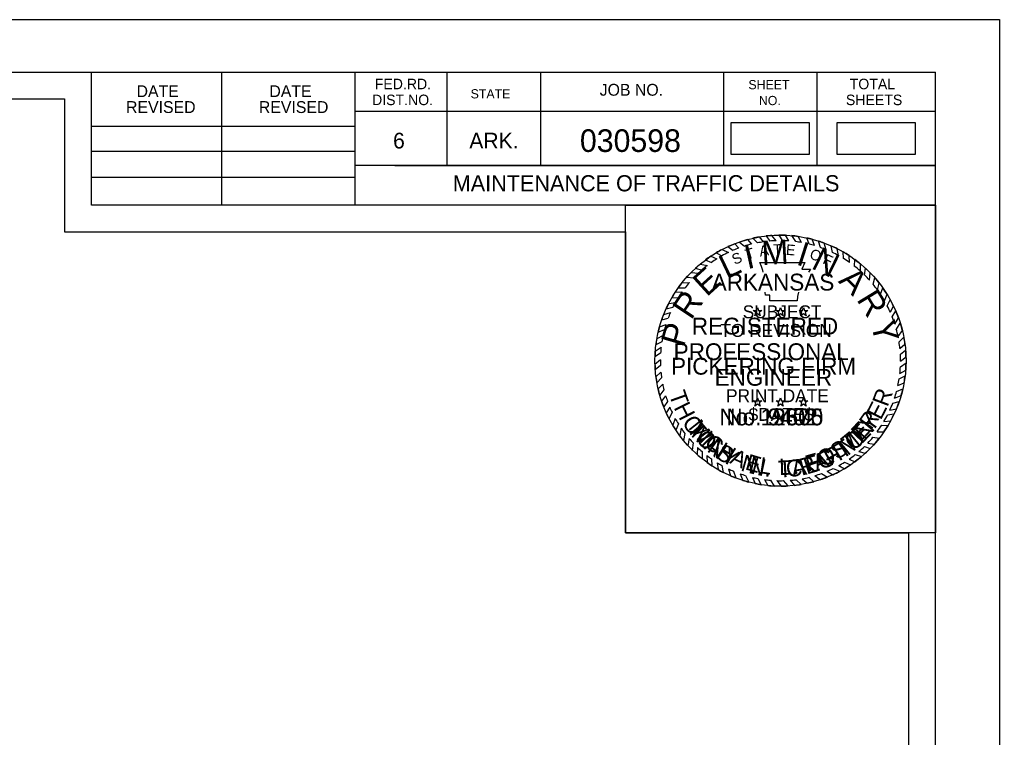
# Model space of a CAD drawing. Extents: x 1368648 to 1927880, y -1037443 to 380209.
# Drawn here: x 1373048.4 to 1373412.1, y 379486.2 to 379752.7 of the extents above; entities that cross this region are included whole.
import ezdxf

# ---------------------------------------------------------------- set-up
doc = ezdxf.new("R2010")
doc.units = 0
for name, color, linetype in [('Default', 7, 'Continuous'), ('R_Border', 7, 'Continuous'), ('R_Border Notes', 7, 'Continuous'), ('R_No Plot', 7, 'Continuous'), ('STAMP_PE_CRAFTON', 7, 'Continuous'), ('STAMP_PE_FOSTER', 7, 'Continuous'), ('STAMP_PE_SEAL-INFO', 7, 'Continuous'), ('STAMP_PE_TAEGTMEYER', 7, 'Continuous'), ('STAMP_PE_TXT', 7, 'Continuous'), ('STAMP_PRELIMINARY', 7, 'Continuous')]:
    doc.layers.add(name, color=color, linetype=linetype)

msp = doc.modelspace()

# ---------------------------------------------------------------- linework, layer by layer
at = {"layer": 'Default'}
for points in [[(1373312.37, 379702.78), (1373341.54, 379702.78), (1373341.54, 379714.33), (1373312.37, 379714.33)], [(1373351.72, 379702.78), (1373380.89, 379702.78), (1373380.89, 379714.33), (1373351.72, 379714.33)]]:
    msp.add_lwpolyline(points, close=True, dxfattribs=at)
at = {"layer": 'R_Border'}
for p, q in [((1371807.4, 379733.26), (1373388.3, 379733.26)), ((1373075.1, 379683.86), (1373075.1, 379733.26)), ((1373123.5, 379683.86), (1373123.5, 379733.26)), ((1373172.8, 379733.26), (1373172.8, 379683.86)), ((1373207, 379733.26), (1373207, 379698.56)), ((1373241.7, 379733.26), (1373241.7, 379698.56)), ((1373309.6, 379733.26), (1373309.6, 379698.56)), ((1373344.3, 379733.26), (1373344.3, 379698.56)), ((1373388.3, 378705.96), (1373388.3, 379733.26)), ((1373388.3, 379718.56), (1373172.8, 379718.56)), ((1373388.3, 379718.66), (1373388.3, 379718.66)), ((1373075.1, 379713.16), (1373172.8, 379713.16)), ((1373075.1, 379703.86), (1373172.8, 379703.86)), ((1373388.3, 379698.56), (1373172.8, 379698.56)), ((1373187.6, 379698.56), (1373388.3, 379698.56)), ((1373075.1, 379694.16), (1373172.8, 379694.16)), ((1373388.3, 379683.86), (1373075.1, 379683.86))]:
    msp.add_line(p, q, dxfattribs=at)
at = {"layer": 'R_No Plot'}
for points in [[(1371745.37, 379752.73), (1373412.07, 379752.73), (1373412.07, 378686.04), (1371745.37, 378686.04)], [(1373378.3, 379229.61), (1371817.4, 379229.61), (1371817.4, 379723.26), (1373065.1, 379723.26), (1373065.1, 379673.86), (1373152.8, 379673.86), (1373273.3, 379673.86), (1373273.3, 379562.19), (1373378.3, 379562.19)], [(1371817.4, 379723.26), (1373065.1, 379723.26), (1373065.1, 379673.86), (1373152.8, 379673.86), (1373273.3, 379673.86), (1373273.3, 379562.19), (1373378.3, 379562.19), (1373378.3, 378715.96), (1371817.4, 378715.96)], [(1373273.3, 379683.86), (1373388.3, 379683.86), (1373388.3, 379562.19), (1373273.3, 379562.19)]]:
    msp.add_lwpolyline(points, close=True, dxfattribs=at)
at = {"layer": 'STAMP_PE_SEAL-INFO'}
for p, q in [((1373313.86, 379669.49), (1373315.34, 379667.87)), ((1373315.6, 379670.13), (1373317.51, 379668.61)), ((1373318.56, 379671.04), (1373320, 379669.31)), ((1373320.5, 379671.53), (1373322.28, 379669.81)), ((1373322.91, 379672.01), (1373324.4, 379670.17)), ((1373325.49, 379672.38), (1373326.89, 379670.46)), ((1373329.16, 379670.61), (1373327.6, 379672.57)), ((1373331.65, 379670.63), (1373330.26, 379672.68)), ((1373333.94, 379670.53), (1373332.65, 379672.65)), ((1373336.47, 379670.27), (1373335.01, 379672.49)), ((1373338.6, 379669.95), (1373337.31, 379672.23)), ((1373341.41, 379669.36), (1373340.54, 379671.65)), ((1373343.42, 379668.81), (1373342.62, 379671.16)), ((1373345.68, 379668.08), (1373344.97, 379670.48)), ((1373347.77, 379667.28), (1373347.05, 379669.76)), ((1373306.93, 379666.1), (1373309.09, 379664.99)), ((1373309.17, 379667.36), (1373311.49, 379666.23)), ((1373311.32, 379668.42), (1373313.27, 379667.04)), ((1373350.08, 379666.25), (1373349.56, 379668.74)), ((1373352.31, 379665.11), (1373351.87, 379667.65)), ((1373354.24, 379663.97), (1373354.04, 379666.48)), ((1373302.89, 379663.55), (1373305.17, 379662.53)), ((1373305, 379664.88), (1373307.2, 379663.87)), ((1373323.17, 379662.52), (1373339.89, 379662.52)), ((1373323.78, 379660.99), (1373323.17, 379662.52)), ((1373339.89, 379662.52), (1373338.77, 379660.07)), ((1373356.42, 379662.54), (1373356.26, 379665.12)), ((1373358.22, 379661.21), (1373358.39, 379663.64)), ((1373297.61, 379658.8), (1373300.33, 379658.59)), ((1373299.29, 379660.41), (1373301.58, 379659.72)), ((1373301.01, 379661.92), (1373303.66, 379661.41)), ((1373324.3, 379659.5), (1373323.78, 379660.99)), ((1373324.33, 379658.93), (1373324.3, 379659.5)), ((1373338.77, 379660.07), (1373341.93, 379660.07)), ((1373341.93, 379660.07), (1373341.2, 379658.93)), ((1373360.45, 379659.35), (1373360.55, 379661.96)), ((1373362.01, 379657.88), (1373362.36, 379660.38)), ((1373363.81, 379656.02), (1373364.14, 379658.65)), ((1373294.27, 379655.02), (1373297.02, 379655.13)), ((1373296, 379657.08), (1373298.61, 379656.88)), ((1373365.18, 379654.44), (1373365.86, 379656.79)), ((1373366.8, 379652.35), (1373367.47, 379654.85)), ((1373291.71, 379651.45), (1373294.29, 379651.62)), ((1373292.88, 379653.17), (1373295.41, 379653.15)), ((1373325.29, 379650.38), (1373325.16, 379651.47)), ((1373337.47, 379651.47), (1373337.09, 379649.92)), ((1373367.9, 379650.77), (1373368.79, 379653.09)), ((1373289.32, 379647.33), (1373291.81, 379647.65)), ((1373290.48, 379649.45), (1373292.92, 379649.55)), ((1373326.86, 379650.38), (1373325.29, 379650.38)), ((1373326.86, 379648.23), (1373326.86, 379650.38)), ((1373337.01, 379648.23), (1373326.86, 379648.23)), ((1373337.09, 379649.92), (1373337.01, 379648.23)), ((1373369.44, 379648.29), (1373370.35, 379650.74)), ((1373370.44, 379646.45), (1373371.57, 379648.68)), ((1373287.46, 379643.22), (1373289.98, 379643.95)), ((1373288.38, 379645.38), (1373290.89, 379645.9)), ((1373371.59, 379644.03), (1373372.72, 379646.46)), ((1373372.29, 379642.35), (1373373.61, 379644.52)), ((1373286.71, 379641.19), (1373289.13, 379641.87)), ((1373373.27, 379639.6), (1373374.62, 379641.98)), ((1373285.41, 379636.64), (1373287.76, 379637.6)), ((1373285.93, 379638.68), (1373288.32, 379639.52)), ((1373373.81, 379637.78), (1373375.27, 379640.04)), ((1373374.47, 379634.99), (1373376.06, 379637.22)), ((1373286.8, 379633.11), (1373284.57, 379632)), ((1373287.23, 379635.41), (1373284.9, 379634.16)), ((1373374.82, 379633.09), (1373376.58, 379634.85)), ((1373286.5, 379630.94), (1373284.32, 379629.53)), ((1373375.15, 379630.54), (1373377.01, 379632.22)), ((1373375.31, 379628.45), (1373377.26, 379629.91)), ((1373286.32, 379628.81), (1373284.21, 379627.53)), ((1373286.24, 379626.34), (1373284.21, 379624.67)), ((1373375.37, 379625.86), (1373377.4, 379627.47)), ((1373286.27, 379624.31), (1373284.31, 379622.68)), ((1373375.12, 379621.3), (1373377.29, 379622.59)), ((1373375.32, 379623.83), (1373377.41, 379625.22)), ((1373286.44, 379621.83), (1373284.58, 379620.05)), ((1373286.7, 379619.69), (1373284.93, 379617.82)), ((1373374.86, 379619.36), (1373377.08, 379620.46)), ((1373287.09, 379617.39), (1373285.39, 379615.55)), ((1373287.56, 379615.3), (1373286, 379613.22)), ((1373373.87, 379614.6), (1373376.23, 379615.61)), ((1373374.41, 379616.86), (1373376.69, 379617.84)), ((1373288.18, 379613.06), (1373286.7, 379610.97)), ((1373373.14, 379612.13), (1373375.59, 379613.14)), ((1373288.88, 379610.95), (1373287.47, 379608.89)), ((1373289.71, 379608.81), (1373288.4, 379606.7)), ((1373371.39, 379607.66), (1373373.83, 379608.14)), ((1373372.46, 379610.23), (1373374.88, 379610.89)), ((1373290.57, 379606.9), (1373289.43, 379604.59)), ((1373291.75, 379604.61), (1373290.79, 379602.16)), ((1373370.59, 379605.98), (1373373.03, 379606.32)), ((1373292.92, 379602.59), (1373292, 379600.23)), ((1373293.94, 379601.03), (1373293.39, 379598.27)), ((1373368.37, 379602.08), (1373370.75, 379602.05)), ((1373369.23, 379603.49), (1373371.73, 379603.76)), ((1373295.34, 379599.08), (1373294.83, 379596.42)), ((1373296.86, 379597.19), (1373296.43, 379594.59)), ((1373365.13, 379597.64), (1373367.44, 379597.24)), ((1373366.67, 379599.61), (1373369.19, 379599.63)), ((1373298.37, 379595.5), (1373298.06, 379592.89)), ((1373299.98, 379593.87), (1373299.84, 379591.23)), ((1373361.94, 379594.18), (1373364.14, 379593.49)), ((1373363.21, 379595.48), (1373365.6, 379595.05)), ((1373301.71, 379592.31), (1373301.69, 379589.67)), ((1373303.51, 379590.84), (1373303.6, 379588.22)), ((1373305.2, 379589.59), (1373305.38, 379587)), ((1373356.25, 379589.48), (1373358.45, 379588.54)), ((1373358.56, 379591.2), (1373360.9, 379590.47)), ((1373359.91, 379592.32), (1373362.27, 379591.67)), ((1373307.33, 379588.18), (1373307.64, 379585.62)), ((1373309.09, 379587.15), (1373309.54, 379584.59)), ((1373311.49, 379585.9), (1373312.27, 379583.3)), ((1373350.42, 379586.05), (1373352.84, 379584.99)), ((1373352.46, 379587.12), (1373354.55, 379585.95)), ((1373354.54, 379588.34), (1373356.78, 379587.37)), ((1373313.35, 379585.06), (1373314.22, 379582.51)), ((1373315.82, 379584.1), (1373316.86, 379581.59)), ((1373317.86, 379583.42), (1373319, 379580.98)), ((1373320.4, 379582.73), (1373321.47, 379580.4)), ((1373322.39, 379582.3), (1373323.62, 379580.01)), ((1373338.81, 379582.23), (1373340.75, 379580.53)), ((1373341.27, 379582.75), (1373343.16, 379581.12)), ((1373343.57, 379583.37), (1373345.65, 379581.88)), ((1373346.03, 379584.18), (1373348.25, 379582.84)), ((1373348.13, 379585.01), (1373350.24, 379583.7)), ((1373324.89, 379581.89), (1373326.09, 379579.69)), ((1373327.08, 379581.66), (1373328.45, 379579.51)), ((1373329.5, 379581.52), (1373331.01, 379579.46)), ((1373331.8, 379581.51), (1373333.52, 379579.53)), ((1373334.39, 379581.65), (1373336.02, 379579.75)), ((1373336.58, 379581.88), (1373338.45, 379580.09))]:
    msp.add_line(p, q, dxfattribs=at)
for radius, start, end in [(46.61, 111.3124, 114.7026), (46.61, 105.2339, 109.0352), (44.57, 104.0352, 107.3615), (46.61, 99.7525, 102.7765), (44.57, 98.258, 101.0329), (46.61, 93.9381, 96.5517), (44.57, 92.1102, 95.0367), (46.61, 87.7298, 90.6707), (44.57, 85.9628, 88.9097), (46.61, 81.9732, 84.8236), (44.57, 79.9264, 82.696), (46.61, 75.3125, 77.9426), (44.57, 73.5575, 76.2314), (46.61, 69.6061, 72.3058), (46.61, 117.6544, 120.8099), (44.57, 115.6869, 119.1583), (44.57, 110.3086, 113.1659), (44.57, 67.6248, 70.504), (46.61, 63.1329, 66.2704), (44.57, 61.1558, 64.3784), (46.61, 56.9003, 60.0942), (46.61, 123.6199, 126.5906), (44.57, 121.9746, 125.11), (44.57, 54.9238, 58.2702), (46.61, 50.3492, 53.7159), (46.61, 135.4021, 138.3031), (44.57, 133.1331, 136.2562), (46.61, 129.7326, 132.5376), (44.57, 127.5297, 130.9683), (44.57, 48.3016, 52.0395), (46.61, 44.3405, 47.3929), (46.61, 141.6056, 144.4486), (44.57, 139.301, 142.5873), (44.57, 42.2212, 45.5512), (46.61, 38.1247, 41.2316), (46.61, 147.0072, 149.899), (44.57, 145.0197, 148.2104), (44.57, 36.135, 39.5311), (46.61, 31.9614, 35.4294), (44.57, 151.0315, 153.573), (44.57, 29.9032, 33.6645), (46.61, 25.9391, 29.0125), (46.61, 152.864, 155.5189), (44.57, 156.3402, 159.2319), (44.57, 23.7732, 27.2211), (46.61, 19.9538, 23.3141), (46.61, 158.4077, 161.0701), (44.57, 17.6802, 21.4251), (46.61, 164.3068, 166.894), (44.57, 162.4331, 165.0013), (44.57, 11.5444, 15.2364), (46.61, 13.8421, 17.4447), (46.61, 170.0003, 172.6878), (44.57, 167.9048, 170.9039), (44.57, 5.7599, 9.0606), (46.61, 7.5852, 10.8621), (46.61, 175.7409, 178.2066), (44.57, 173.73, 176.4734), (46.61, 1.7215, 4.7268), (44.57, 179.6454, 182.2633), (44.57, 359.7329, 3.0639), (46.61, 181.7251, 184.1626), (44.57, 353.8632, 357.1274), (46.61, 355.7156, 358.9569), (46.61, 187.4204, 190.1927), (44.57, 185.4539, 188.234), (44.57, 348.0778, 351.3435), (46.61, 349.8305, 353.0885), (46.61, 193.0369, 195.9973), (44.57, 191.2274, 193.9858), (46.61, 343.8925, 347.035), (44.57, 196.9675, 199.8353), (44.57, 341.777, 345.0925), (46.61, 198.8967, 201.6281), (44.57, 202.7761, 205.4791), (44.57, 335.6038, 339.1858), (46.61, 337.3837, 340.9933), (46.61, 204.5479, 207.4328), (44.57, 208.7883, 211.7934), (44.57, 329.5549, 333.2076), (46.61, 331.4037, 334.9332), (46.61, 210.8636, 213.6571), (44.57, 214.1838, 217.2747), (44.57, 323.5851, 327.4407), (46.61, 325.4405, 328.9872), (46.61, 216.6115, 219.491), (44.57, 220.3909, 223.3056), (44.57, 316.6531, 320.3711), (46.61, 318.2846, 321.8043), (46.61, 222.48, 225.3801), (44.57, 226.2494, 229.2407), (44.57, 310.7744, 314.3161), (46.61, 312.4518, 315.6633), (46.61, 228.3665, 231.348), (44.57, 232.229, 234.9336), (44.57, 304.823, 308.5143), (46.61, 306.3721, 310.208), (46.61, 234.295, 236.9452), (44.57, 238.2223, 240.8353), (46.61, 240.1977, 242.8613), (44.57, 244.3204, 246.9486), (44.57, 292.8745, 296.1185), (44.57, 299.0768, 302.1724), (46.61, 300.621, 303.8703), (46.61, 246.576, 249.1558), (44.57, 250.3491, 253.1216), (44.57, 256.505, 259.1192), (44.57, 280.3459, 283.5814), (44.57, 286.6423, 289.9783), (46.61, 288.5709, 291.9733), (46.61, 294.6481, 298.2166), (46.61, 252.5967, 255.3252), (46.61, 258.4433, 261.1398), (44.57, 262.3783, 265.2012), (46.61, 264.1978, 267.1009), (44.57, 268.3215, 271.277), (46.61, 270.2548, 273.3361), (44.57, 274.6157, 277.4486), (46.61, 276.4239, 279.4357), (46.61, 282.3199, 285.3702)]:
    msp.add_arc((1373330.8, 379626.07), radius, start, end, dxfattribs=at)
at = {"layer": 'STAMP_PE_TXT'}
for p, q in [((1373321.7, 379643.93), (1373320.71, 379644.65)), ((1373320.71, 379644.65), (1373321.94, 379644.65)), ((1373321.32, 379642.76), (1373321.7, 379643.93)), ((1373321.94, 379644.65), (1373322.31, 379645.81)), ((1373322.31, 379645.81), (1373322.69, 379644.65)), ((1373322.69, 379644.65), (1373323.92, 379644.65)), ((1373323.92, 379644.65), (1373322.93, 379643.93)), ((1373322.93, 379643.93), (1373323.31, 379642.76)), ((1373330.19, 379643.93), (1373329.2, 379644.65)), ((1373329.2, 379644.65), (1373330.43, 379644.65)), ((1373329.81, 379642.76), (1373330.19, 379643.93)), ((1373330.43, 379644.65), (1373330.8, 379645.81)), ((1373330.8, 379645.81), (1373331.18, 379644.65)), ((1373331.18, 379644.65), (1373332.41, 379644.65)), ((1373332.41, 379644.65), (1373331.42, 379643.93)), ((1373331.42, 379643.93), (1373331.8, 379642.76)), ((1373338.68, 379643.93), (1373337.69, 379644.65)), ((1373337.69, 379644.65), (1373338.92, 379644.65)), ((1373338.3, 379642.76), (1373338.68, 379643.93)), ((1373338.92, 379644.65), (1373339.29, 379645.81)), ((1373339.29, 379645.81), (1373339.67, 379644.65)), ((1373339.67, 379644.65), (1373340.9, 379644.65)), ((1373340.9, 379644.65), (1373339.91, 379643.93)), ((1373339.91, 379643.93), (1373340.29, 379642.76)), ((1373322.31, 379643.48), (1373321.32, 379642.76)), ((1373323.31, 379642.76), (1373322.31, 379643.48)), ((1373330.8, 379643.48), (1373329.81, 379642.76)), ((1373331.8, 379642.76), (1373330.8, 379643.48)), ((1373339.29, 379643.48), (1373338.3, 379642.76)), ((1373340.29, 379642.76), (1373339.29, 379643.48)), ((1373321.7, 379610.39), (1373320.71, 379611.11)), ((1373320.71, 379611.11), (1373321.94, 379611.11)), ((1373321.94, 379611.11), (1373322.31, 379612.28)), ((1373322.31, 379612.28), (1373322.69, 379611.11)), ((1373322.69, 379611.11), (1373323.92, 379611.11)), ((1373323.92, 379611.11), (1373322.93, 379610.39)), ((1373330.19, 379610.39), (1373329.2, 379611.11)), ((1373329.2, 379611.11), (1373330.43, 379611.11)), ((1373330.43, 379611.11), (1373330.8, 379612.28)), ((1373330.8, 379612.28), (1373331.18, 379611.11)), ((1373331.18, 379611.11), (1373332.41, 379611.11)), ((1373332.41, 379611.11), (1373331.42, 379610.39)), ((1373338.68, 379610.39), (1373337.69, 379611.11)), ((1373337.69, 379611.11), (1373338.92, 379611.11)), ((1373338.92, 379611.11), (1373339.29, 379612.28)), ((1373339.29, 379612.28), (1373339.67, 379611.11)), ((1373339.67, 379611.11), (1373340.9, 379611.11)), ((1373340.9, 379611.11), (1373339.91, 379610.39)), ((1373321.32, 379609.22), (1373321.7, 379610.39)), ((1373322.31, 379609.95), (1373321.32, 379609.22)), ((1373323.31, 379609.22), (1373322.31, 379609.95)), ((1373322.93, 379610.39), (1373323.31, 379609.22)), ((1373329.81, 379609.22), (1373330.19, 379610.39)), ((1373330.8, 379609.95), (1373329.81, 379609.22)), ((1373331.8, 379609.22), (1373330.8, 379609.95)), ((1373331.42, 379610.39), (1373331.8, 379609.22)), ((1373338.3, 379609.22), (1373338.68, 379610.39)), ((1373339.29, 379609.95), (1373338.3, 379609.22)), ((1373340.29, 379609.22), (1373339.29, 379609.95)), ((1373339.91, 379610.39), (1373340.29, 379609.22))]:
    msp.add_line(p, q, dxfattribs=at)
at = {"layer": 'STAMP_PRELIMINARY'}
msp.add_circle((1373330.8, 379626.07), 46.61, dxfattribs=at)

# ---------------------------------------------------------------- texts
at = {"layer": 'R_Border'}
for s, height, p in [('DATE', 4.396, (1373091.79, 379723.94)), ('DATE', 4.396, (1373141.09, 379723.94)), ('FED.RD.', 3.91, (1373180.2, 379726.86)), ('JOB NO.', 4.396, (1373263.7, 379724.46)), ('SHEET', 3.42, (1373318.9, 379726.86)), ('TOTAL', 3.91, (1373356.5, 379726.86)), ('DIST.NO.', 3.91, (1373179.2, 379720.96)), ('STATE', 3.42, (1373215.8, 379723.46)), ('NO.', 3.42, (1373322.8, 379720.96)), ('SHEETS', 3.91, (1373355.1, 379720.96)), ('REVISED', 4.396, (1373087.89, 379718.04)), ('REVISED', 4.396, (1373137.19, 379718.04)), ('6', 5.86, (1373187, 379704.86)), ('ARK.', 5.861, (1373215.3, 379704.86))]:
    msp.add_text(s, height=height, dxfattribs=at).set_placement(p)
at = {"layer": 'R_Border Notes'}
for s, height, p in [('030598', 8.4, (1373256.36, 379703.58)), ('MAINTENANCE OF TRAFFIC DETAILS', 6, (1373209.15, 379688.95))]:
    msp.add_text(s, height=height, dxfattribs=at).set_placement(p)
at = {"layer": 'STAMP_PE_CRAFTON'}
msp.add_text('No. 12370', height=6.25, dxfattribs=at).set_placement((1373308.11, 379602.05))
for s, rotation, p in [('T', 310.7442, (1373295.63, 379600.56)), ('N', 49.2411, (1373362.22, 379596.18)), ('O', 317.6422, (1373298.97, 379596.5)), ('N', 324.4537, (1373303.2, 379592.58)), ('T', 34.1136, (1373353.69, 379589.26)), ('O', 41.8391, (1373357.98, 379592.27)), ('Y', 331.1686, (1373308.36, 379589)), ('F', 28.7821, (1373349.11, 379586.72)), ('N', 347.4752, (1373318.64, 379584.42)), ('C', 6.0117, (1373333.16, 379582.77)), ('R', 14.8189, (1373338.64, 379583.35)), ('A', 20.5125, (1373344.21, 379584.85)), ('.', 356.8926, (1373324.78, 379583.03))]:
    msp.add_text(s, height=6.25, rotation=rotation, dxfattribs=at).set_placement(p)
at = {"layer": 'STAMP_PE_FOSTER'}
msp.add_text('No. 9402', height=6.25, dxfattribs=at).set_placement((1373310.73, 379602.05))
for s, rotation, p in [('M', 308.339, (1373296.38, 379601.18)), ('R', 54.5031, (1373364.43, 379600.12)), ('E', 46.9613, (1373360.81, 379596.02)), ('I', 314.1842, (1373300.37, 379596.49)), ('C', 319.8733, (1373302.14, 379594.72)), ('T', 39.4194, (1373356.52, 379592.27)), ('H', 327.7235, (1373306.79, 379591.04)), ('O', 23.719, (1373346.2, 379586.48)), ('S', 31.7234, (1373351.76, 379589.13)), ('A', 335.7276, (1373311.69, 379588.13)), ('E', 343.5779, (1373317.38, 379585.78)), ('L', 350.8115, (1373322.67, 379584.39)), ('L', 1.2666, (1373330.37, 379583.61)), ('F', 15.8691, (1373340.98, 379584.84)), ('.', 6.8035, (1373335.6, 379583.9))]:
    msp.add_text(s, height=6, rotation=rotation, dxfattribs=at).set_placement(p)
at = {"layer": 'STAMP_PE_TAEGTMEYER'}
for s, rotation, p in [('T', 289.646, (1373289.28, 379613.62)), ('R', 69.57, (1373370.53, 379608.64)), ('H', 296.7339, (1373291.08, 379608.7)), ('E', 63.0984, (1373368.04, 379603.73)), ('O', 303.7708, (1373294.04, 379603.16)), ('Y', 53.9986, (1373364.69, 379599.03)), ('M', 314.2033, (1373297.31, 379598.4)), ('E', 46.8094, (1373361, 379594.95)), ('A', 321.0594, (1373302.12, 379593.58)), ('M', 39.3, (1373355.79, 379590.56)), ('S', 327.8239, (1373306.25, 379590.36)), ('T', 31.466, (1373351.3, 379587.84)), ('N', 344.2727, (1373315.74, 379585.33)), ('A', 8.9826, (1373335.36, 379582.95)), ('E', 17.6836, (1373340.55, 379583.73)), ('G', 23.3052, (1373345.8, 379585.38)), ('T', 3.0061, (1373330.13, 379582.67)), ('.', 350.6464, (1373321.8, 379583.67))]:
    msp.add_text(s, height=6.25, rotation=rotation, dxfattribs=at).set_placement(p)
msp.add_text('No. 19605', height=6.25, dxfattribs=at).set_placement((1373308.11, 379602.05))
at = {"layer": 'STAMP_PE_TXT'}
for s, rotation, p in [('T', 1.8248, (1373328.16, 379665.36)), ('S', 23.5541, (1373313.8, 379661.59)), ('T', 16.311, (1373318.41, 379663.45)), ('A', 9.0679, (1373323.22, 379664.71)), ('E', 355.2002, (1373332.71, 379665.4)), ('O', 342.2506, (1373341.34, 379664.02)), ('F', 335.0075, (1373346.17, 379662.33))]:
    msp.add_text(s, height=3.91, rotation=rotation, dxfattribs=at).set_placement(p)
for s, p in [('ARKANSAS', (1373305.27, 379652.12)), ('REGISTERED', (1373297.89, 379635.77)), ('PROFESSIONAL', (1373291.15, 379626.27)), ('ENGINEER', (1373306.35, 379616.76))]:
    msp.add_text(s, height=6.25, dxfattribs=at).set_placement(p)
at = {"layer": 'STAMP_PRELIMINARY'}
for s, rotation, p in [('I', 12.5248, (1373318.49, 379660)), ('M', 3.1074, (1373323.98, 379661.55)), ('I', 342.3164, (1373336.32, 379661.88)), ('N', 333.9382, (1373341.86, 379660.51)), ('L', 25.513, (1373310.85, 379656.21)), ('E', 42.3578, (1373303.43, 379649.55)), ('A', 315.6579, (1373352.03, 379655.39)), ('R', 56.2292, (1373297.66, 379640.89)), ('R', 301.3831, (1373358.87, 379648.82)), ('Y', 283.2593, (1373364.31, 379639.88)), ('P', 73.913, (1373294.91, 379630.77))]:
    msp.add_text(s, height=9, rotation=rotation, dxfattribs=at).set_placement(p)
for s, height, p in [('SUBJECT', 4.8, (1373316.8, 379641.81)), ('TO REVISION', 4.8, (1373308.48, 379634.89)), ('PICKERING FIRM', 6.25, (1373290.17, 379620.88)), ('PRINT DATE', 4.8, (1373310.59, 379610.65)), ('$DATE$', 4.8, (1373318.97, 379603.72))]:
    msp.add_text(s, height=height, dxfattribs=at).set_placement(p)

doc.saveas('drawing.dxf')
